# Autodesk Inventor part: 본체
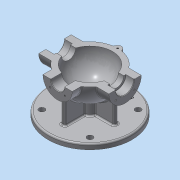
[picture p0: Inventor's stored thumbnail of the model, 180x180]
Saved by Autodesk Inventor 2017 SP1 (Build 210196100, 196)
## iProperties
Created: 2015-12
Part Number: 본체
Material: 알루미늄 6061
Document SubType Name: Modeling
Designer: mduedu
Density: 2.71 g/cm^3
Appearance: 알루미늄 - 평지
Mass: 1042.75 g
Surface Area: 959.747 cm^2
Volume: 384.779 cm^3
Author: mduedu
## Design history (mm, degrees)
sketch "스케치1"
  geometry: L1 (-53, 0)-(53, 0); A1 r 53 centre (0, 0) between (53, 0) and (-53, 0); 2 further points
  constraints: 2 coincident, 2 end point, 2 point on circle, 1 centre point, 1 horizontal, 1 midpoint
  dimensions: "d0" = 53 radius of A1
revolve "회전1" sketch "스케치1" stored, may be unused: angle "d2" = 90 deg
feature "쉘1" dims "d11" = 10
node "작업 평면1"
sketch "스케치2"
  geometry: C1 r 31 at (0, 0); 1 further point
  constraints: 1 centre point, 1 coincident
  dimensions: "d4" = 62 diameter of C1
extrude "돌출1" join sketch "스케치2" stored distance "d5" = 10; taper "d6" = 0 deg
node "작업 평면2"
sketch "스케치3"
  geometry: C1 r 28 at (0, 0); 1 further point
  constraints: 1 centre point, 1 coincident
  dimensions: "d8" = 56 diameter of C1
extrude "돌출2" join sketch "스케치3" stored distance "d9" = 10; taper "d10" = 0 deg
hole "구멍1" diameter "d14" = 35; stored, may be unused: countersink angle "d18" = 90 deg, drill point angle "d20" = 0 deg; dims "d12" = 10, "d13" = 10, "d15" = 6, "d16" = 4, "d17" = 2, "d19" = 16
hole "구멍2" diameter "d23" = 27; stored, may be unused: countersink angle "d27" = 90 deg, drill point angle "d29" = 0 deg; dims "d21" = 10, "d22" = 10, "d24" = 6, "d25" = 4, "d26" = 2, "d28" = 16
fillet "모깎기1" dims "d30" = 0.3
hole "구멍3" diameter "d33" = 26; stored, may be unused: countersink angle "d37" = 90 deg, drill point angle "d39" = 0 deg; dims "d31" = 10, "d32" = 10, "d34" = 6, "d35" = 4, "d36" = 2, "d38" = 16
chamfer "모따기1" distance "d40" = 1; stored, may be unused: second distance "d41" = 2, angle "d42" = 45 deg
sketch "스케치4"
  geometry: L1 (0, 0)-(0, -25); L2 (0, 0)-(-17.678, -17.678); A1 r 25 centre (0, 0) between (-17.678, -17.678) and (0, -25); 1 further point
  constraints: 4 end point, 2 point on circle, 1 centre point, 1 coincident, 1 vertical
  dimensions: "d43" = 50 diameter of A1; "d47" = 45 deg angle of L1 L2
hole "구멍4" sketch "스케치4" at (-17.678, -17.678) diameter "d49" = 3.242; stored, may be unused: countersink angle "d53" = 90 deg, drill point angle "d55" = 118 deg; dims "d50" = 11, "d51" = 4, "d52" = 2, "d54" = 13
sketch "스케치5"
  geometry: L1 (0, 0)-(0, -20); L2 (0, 0)-(-14.142, -14.142); A1 r 20 centre (0, 0) between (0, -20) and (-14.142, -14.142); 2 further points
  constraints: 4 end point, 2 coincident, 2 point on circle, 1 centre point, 1 vertical
  dimensions: "d59" = 40 diameter of A1; "d65" = 45 deg angle of L1 L2
hole "구멍5" sketch "스케치5" at (-14.142, -14.142) diameter "d67" = 3.242; stored, may be unused: countersink angle "d71" = 90 deg, drill point angle "d73" = 118 deg; dims "d68" = 8, "d69" = 4, "d70" = 2, "d72" = 10
node "작업 평면3"
sketch "스케치6"
  geometry: C1 r 80 at (0, 0); 1 further point
  constraints: 1 centre point, 1 coincident
  dimensions: "d78" = 160 diameter of C1
extrude "돌출3" join sketch "스케치6" distance "d80" = 10; taper "d81" = 0 deg
sketch "스케치7"
  geometry: C1 r 15 at (0, 0); 1 further point
  constraints: 1 centre point, 1 coincident
  dimensions: "d82" = 30 diameter of C1
extrude "돌출4" join sketch "스케치7" stored distance "d84" = 10; taper "d85" = 0 deg
sketch "스케치8"
  geometry: 2 further points
  constraints: 1 coincident
hole "구멍6" sketch "스케치8" at (0, 0) diameter "d86" = 20; stored, may be unused: countersink angle "d90" = 90 deg, drill point angle "d92" = 118 deg; dims "d87" = 7, "d88" = 100, "d89" = 5, "d91" = 10
fillet "모깎기2" dims "d93" = 0.3
sketch "스케치9"
  geometry: L1 (-67, -18.5)-(-66, -17.5) reference; L2 (-66, -17.5)-(-51.3, -17.5) reference; L3 (-51, -17.2)-(-51, -13.5) reference; L4 (-51, -13.5)-(-40.826, -13.5) reference; L5 (-10, -41.821)-(-10, -80) reference; L6 (-10, -80)-(-49.7, -80) reference; L7 (-50, -80.3)-(-50, -85) reference; L8 (-50, -85)-(-80, -85) reference; L9 (-80, -85)-(-80, -75) reference; L10 (-80, -75)-(-15, -75) reference; L11 (-15, -75)-(-15, -50.833) reference; L12 (-42.988, -31)-(-67, -31) reference; L13 (-67, -31)-(-67, -18.5) reference; L14 (66, -17.5)-(67, -18.5) reference; L15 (67, -18.5)-(67, -31) reference; L16 (67, -31)-(42.988, -31) reference; L17 (15, -50.833)-(15, -75) reference; L18 (15, -75)-(80, -75) reference; L19 (80, -75)-(80, -85) reference; L20 (80, -85)-(50, -85) reference; L21 (50, -85)-(50, -80.3) reference; L22 (49.7, -80)-(10, -80) reference; L23 (10, -80)-(10, -41.821) reference; L24 (40.826, -13.5)-(51, -13.5) reference; L25 (51, -13.5)-(51, -17.2) reference; L26 (51.3, -17.5)-(66, -17.5) reference; L27 (67, 18.5)-(66, 17.5) reference; L28 (66, 17.5)-(51.3, 17.5) reference; L29 (51, 17.2)-(51, 13.5) reference; L30 (51, 13.5)-(40.826, 13.5) reference; L31 (-40.826, 13.5)-(-51, 13.5) reference; L32 (-51, 13.5)-(-51, 17.2) reference; L33 (-51.3, 17.5)-(-66, 17.5) reference; L34 (-66, 17.5)-(-67, 18.5) reference; L35 (-67, 18.5)-(-67, 31) reference; L36 (-67, 31)-(-42.988, 31) reference; L37 (42.988, 31)-(67, 31) reference; L38 (67, 31)-(67, 18.5) reference; L39 (-50, -31)-(-50, -75); A1 r 0.3 centre (-51.3, -17.2) between (-51.3, -17.5) and (-51, -17.2) reference; A2 r 43 centre (0, 0) between (-40.826, -13.5) and (-10, -41.821) reference; A3 r 0.3 centre (-49.7, -80.3) between (-49.7, -80) and (-50, -80.3) reference; A4 r 53 centre (0, 0) between (-42.988, -31) and (-15, -50.833) reference; A5 r 53 centre (0, 0) between (15, -50.833) and (42.988, -31) reference; A6 r 0.3 centre (49.7, -80.3) between (50, -80.3) and (49.7, -80) reference; A7 r 43 centre (0, 0) between (10, -41.821) and (40.826, -13.5) reference; A8 r 0.3 centre (51.3, -17.2) between (51, -17.2) and (51.3, -17.5) reference; A9 r 0.3 centre (51.3, 17.2) between (51.3, 17.5) and (51, 17.2) reference; A10 r 43 centre (0, 0) between (40.826, 13.5) and (-40.826, 13.5) reference; A11 r 0.3 centre (-51.3, 17.2) between (-51, 17.2) and (-51.3, 17.5) reference; A12 r 53 centre (0, 0) between (42.988, 31) and (-42.988, 31) reference; 1 further point
  constraints: 2 end point, 2 point on line
  dimensions: "d173" = 30 distance from line of L39.end L9; "d174" = 90 deg angle of L10 L39
feature "리브1" sketch "스케치9" dims "d96" = 1, "d97" = 8, "d98" = 0, "d99" = 0, "d100" = 1, "d101" = 1
sketch "스케치14"
  geometry: L1 (-14, 62)-(-13, 61) reference; L2 (-13, 61)-(-13, 40.988) reference; L3 (-41.821, 10)-(-80, 10) reference; L4 (-80, 10)-(-80, 49.7) reference; L5 (-80.3, 50)-(-85, 50) reference; L6 (-85, 50)-(-85, 80) reference; L7 (-85, 80)-(-75, 80) reference; L8 (-75, 80)-(-75, 15) reference; L9 (-75, 15)-(-50.833, 15) reference; L10 (-28, 45)-(-28, 62) reference; L11 (-28, 62)-(-14, 62) reference; L12 (13, 61)-(14, 62) reference; L13 (14, 62)-(28, 62) reference; L14 (28, 62)-(28, 45) reference; L15 (-50.833, -15)-(-75, -15) reference; L16 (-75, -15)-(-75, -80) reference; L17 (-75, -80)-(-85, -80) reference; L18 (-85, -80)-(-85, -50) reference; L19 (-85, -50)-(-80.3, -50) reference; L20 (-80, -49.7)-(-80, -10) reference; L21 (-80, -10)-(-41.821, -10) reference; L22 (13, 40.988)-(13, 61) reference; L23 (-28, 52)-(-75, 52); A1 r 43 centre (0, 0) between (-13, 40.988) and (-41.821, 10) reference; A2 r 0.3 centre (-80.3, 49.7) between (-80, 49.7) and (-80.3, 50) reference; A3 r 53 centre (0, 0) between (-28, 45) and (-50.833, 15) reference; A4 r 53 centre (0, 0) between (0, -53) and (28, 45) reference; A5 r 53 centre (0, 0) between (-50.833, -15) and (0, -53) reference; A6 r 0.3 centre (-80.3, -49.7) between (-80.3, -50) and (-80, -49.7) reference; A7 r 43 centre (0, 0) between (-41.821, -10) and (0, -43) reference; A8 r 43 centre (0, 0) between (0, -43) and (13, 40.988) reference; 1 further point
  constraints: 2 end point, 2 point on line
  dimensions: "d175" = 28 distance of L7.end L23.end; "d176" = 90 deg angle of L8 L23
feature "리브2" sketch "스케치14" dims "d153" = 1, "d154" = 8, "d155" = 0, "d156" = 0, "d157" = 1, "d158" = 1
sketch "스케치10"
  geometry: L1 (0, 0)-(0, -65); L2 (0, 0)-(-45.962, -45.962); A1 r 65 centre (0, 0) between (0, -65) and (-45.962, -45.962); 2 further points
  constraints: 4 end point, 2 coincident, 2 point on circle, 1 centre point, 1 vertical
  dimensions: "d105" = 130 diameter of A1; "d107" = 45 deg angle of L1 L2
hole "구멍7" sketch "스케치10" at (-45.962, -45.962) diameter "d109" = 11; stored, may be unused: countersink angle "d113" = 90 deg, drill point angle "d115" = 118 deg; dims "d110" = 7, "d111" = 18, "d112" = 4, "d114" = 10
fillet "모깎기3" dims "d120" = 3
fillet "모깎기4" dims "d121" = 3, "d122" = 3
fillet "모깎기5" dims "d123" = 3
fillet "모깎기6" dims "d124" = 3
sketch "스케치11"
  geometry: C1 r 80 at (0, 0) reference; C2 r 65 at (0, 0)
  constraints: 1 centre point, 1 coincident, 1 other
  dimensions: "d161" = 130 diameter of C2
feature "엠보싱1" sketch "스케치11" dims "d11" = 10, "d125" = 0.5, "d126" = 0
sketch "스케치12"
  geometry: L1 (0, 100)-(0, -100); L2 (0, 100)-(100, 100); L3 (100, 100)-(100, -100); L4 (100, -100)-(0, -100); 2 further points
  constraints: 8 end point, 3 perpendicular, 1 coincident, 1 midpoint, 1 vertical
  dimensions: "d127" = 200 distance of L2.end L3.end; "d129" = 100 distance between parallel lines of L1 L3
extrude "돌출5" cut sketch "스케치12" stored distance "d130" = 10; taper "d131" = 0 deg
sketch "스케치13"
  geometry: C1 r 7 at (0, 53); A1 r 53 centre (0, 0) between (42.113, 32.179) and (-42.113, 32.179) reference; 1 further point
  constraints: 1 centre point, 1 point on circle
  dimensions: "d132" = 14 diameter of C1
extrude "돌출6" join sketch "스케치13" distance "d134" = 15; taper "d135" = 0 deg
hole "구멍8" diameter "d139" = 3.242; stored, may be unused: countersink angle "d143" = 90 deg, drill point angle "d145" = 118 deg; dims "d140" = 8, "d141" = 4, "d142" = 2, "d144" = 10, "d148" = 10, "d149" = 10
fillet "모깎기7" dims "d146" = 3
fillet "모깎기8" dims "d147" = 3
node "솔리드1"
mirror "대칭1"
mirror "대칭2"
pattern_circular "원형 패턴1" dims angle "d57" = 360 deg
mirror "대칭3"
pattern_circular "원형 패턴2" dims angle "d75" = 360 deg
mirror "대칭4"
pattern_circular "원형 패턴4" dims angle "d118" = 360 deg
node "절단 모서리 투영1"
node "절단 모서리 투영2"
other parameters: "d3" = 67, "d7" = 62, "d77" = -85
